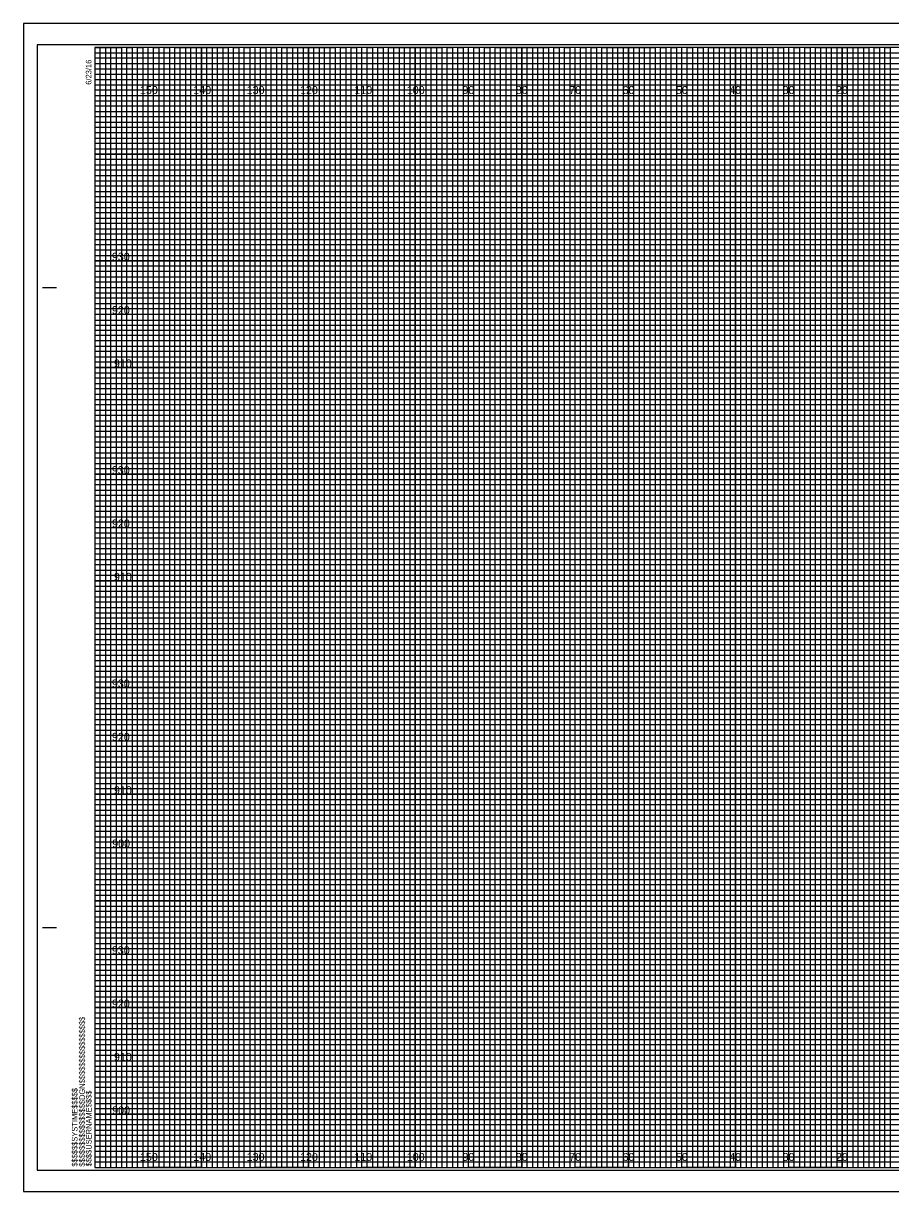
# Model space of a CAD drawing. Extents: x -13 to 323, y -4 to 3074.
# Drawn here: x -13.4 to 149.1, y 215.5 to 434.5 of the extents above; entities that cross this region are included whole.
import ezdxf

# ---------------------------------------------------------------- set-up
doc = ezdxf.new("R2010")
doc.units = 0
for name, color, linetype in [('Prop XS Elevation Labels', 7, 'Continuous'), ('Prop XS Offset Labels', 7, 'Continuous'), ('Sheet Cross Section CELL', 7, 'Continuous'), ('Sheet Cross Section Grid Major CELL', 7, 'Continuous'), ('Sheet Cross Section Grid Middle CELL', 7, 'Continuous'), ('Sheet Cross Section Grid Minor 1 CELL', 7, 'Continuous'), ('Sheet Cross Section Grid Minor 2 CELL', 7, 'Continuous'), ('Sheet Cutting Line CELL', 7, 'Continuous'), ('Sheet DOT Grid CELL', 7, 'Continuous'), ('Sheet Plot Border Inside CELL', 7, 'Continuous'), ('Sheet Plot Border Outside CELL', 7, 'Continuous')]:
    doc.layers.add(name, color=color, linetype=linetype)

msp = doc.modelspace()

# ---------------------------------------------------------------- linework, layer by layer
at = {"layer": 'Sheet Cross Section CELL'}
for p, q in [((-9.8, 385), (-7.3, 385)), ((-9.7, 385), (-7.2, 385)), ((-9.8, 265), (-7.3, 265)), ((-9.7, 265), (-7.2, 265)), ((0, 220), (0, 220)), ((0, 220), (0, 220)), ((0, 220), (0, 220)), ((0, 220), (0, 220)), ((0, 220), (0, 220)), ((0, 220), (0, 220)), ((0, 220), (0, 220))]:
    msp.add_line(p, q, dxfattribs=at)
msp.add_lwpolyline([(320, 430), (0, 430), (0, 220), (320, 220)], close=True, dxfattribs=at)
at = {"layer": 'Sheet Cross Section Grid Major CELL'}
for p, q in [((10, 430), (0, 430)), ((10, 220), (10, 430)), ((30, 430), (20, 430)), ((20, 430), (20, 220)), ((30, 220), (30, 430)), ((50, 430), (40, 430)), ((40, 430), (40, 220)), ((50, 220), (50, 430)), ((70, 430), (60, 430)), ((60, 430), (60, 220)), ((70, 220), (70, 430)), ((90, 430), (80, 430)), ((80, 430), (80, 220)), ((90, 220), (90, 430)), ((110, 430), (100, 430)), ((100, 430), (100, 220)), ((110, 220), (110, 430)), ((130, 430), (120, 430)), ((120, 430), (120, 220)), ((130, 220), (130, 430)), ((150, 430), (140, 430)), ((140, 430), (140, 220)), ((20, 220), (10, 220)), ((40, 220), (30, 220)), ((60, 220), (50, 220)), ((80, 220), (70, 220)), ((100, 220), (90, 220)), ((120, 220), (110, 220)), ((140, 220), (130, 220))]:
    msp.add_line(p, q, dxfattribs=at)
for points in [[(0, 420), (320, 420), (320, 410), (0, 410)], [(0, 400), (320, 400), (320, 390), (0, 390)], [(0, 380), (320, 380), (320, 370), (0, 370)], [(0, 360), (320, 360), (320, 350), (0, 350)], [(0, 340), (320, 340), (320, 330), (0, 330)], [(0, 320), (320, 320), (320, 310), (0, 310)], [(0, 300), (320, 300), (320, 290), (0, 290)], [(0, 280), (320, 280), (320, 270), (0, 270)], [(0, 260), (320, 260), (320, 250), (0, 250)], [(0, 240), (320, 240), (320, 230), (0, 230)]]:
    msp.add_lwpolyline(points, dxfattribs=at)
at = {"layer": 'Sheet Cross Section Grid Middle CELL'}
for points in [[(0, 430), (5, 430), (5, 220), (15, 220), (15, 430), (25, 430), (25, 220), (35, 220), (35, 430), (45, 430), (45, 220), (55, 220), (55, 430), (65, 430), (65, 220), (75, 220), (75, 430), (85, 430), (85, 220), (95, 220), (95, 430), (105, 430), (105, 220), (115, 220), (115, 430), (125, 430), (125, 220), (135, 220), (135, 430), (145, 430), (145, 220), (155, 220)], [(0, 425), (275, 425)], [(0, 405), (320, 405), (320, 415), (0, 415)], [(0, 385), (320, 385), (320, 395), (0, 395)], [(0, 365), (320, 365), (320, 375), (0, 375)], [(0, 345), (320, 345), (320, 355), (0, 355)], [(0, 325), (320, 325), (320, 335), (0, 335)], [(0, 305), (320, 305), (320, 315), (0, 315)], [(0, 285), (320, 285), (320, 295), (0, 295)], [(0, 265), (320, 265), (320, 275), (0, 275)], [(0, 245), (320, 245), (320, 255), (0, 255)], [(0, 225), (320, 225), (320, 235), (0, 235)]]:
    msp.add_lwpolyline(points, dxfattribs=at)
at = {"layer": 'Sheet Cross Section Grid Minor 1 CELL'}
for p, q in [((0, 429), (260, 429)), ((260, 427.98), (0, 427.98)), ((0, 427.98), (0, 427)), ((0, 427), (260, 427)), ((260, 425.89), (0, 425.89)), ((0, 425.89), (0, 424)), ((0, 424), (320, 424))]:
    msp.add_line(p, q, dxfattribs=at)
for points in [[(0, 423), (270, 423), (320, 423), (320, 422), (0, 422)], [(0, 421), (320, 421), (320, 419), (0, 419)], [(0, 418), (320, 418), (320, 417), (0, 416.98)], [(0, 416), (320, 416), (320, 414), (0, 414)], [(0, 413), (320, 413), (320, 412), (0, 412)], [(0, 411), (320, 411), (320, 409), (0, 409)], [(0, 408), (320, 408), (320, 407), (0, 407)], [(0, 406), (320, 406), (320, 404), (0, 404)], [(0, 403), (320, 403), (320, 402), (0, 402)], [(0, 401), (320, 401), (320, 399), (0, 399)], [(0, 398), (320, 398), (320, 397), (0, 397)], [(0, 396), (320, 396), (320, 393.95), (320, 393), (320, 392), (0, 392)], [(0, 394), (320, 394), (320, 393), (0, 393)], [(0, 391), (320, 391), (320, 389), (0, 389.03)], [(0, 389.03), (320, 389), (320, 388), (0, 388)], [(0, 387), (320, 387), (320, 386), (0, 386)], [(0, 384), (320, 384), (320, 383), (0, 383)], [(0, 382), (320, 382), (320, 381), (0, 381)], [(-0.07, 378.89), (320, 378.89), (320, 377.88), (-0.07, 377.88)], [(0, 377), (320, 377), (320, 376), (0, 376)], [(0, 374), (320, 374), (320, 373), (0, 373)], [(0, 372), (320, 372), (320, 371), (0, 371)], [(0, 369), (320, 369), (320, 368), (0, 368)], [(0, 367), (320, 367), (320, 366), (0, 366)], [(0, 364), (320, 364), (320, 363), (0, 363)], [(0, 362), (320, 362), (320, 361), (0, 361)], [(0, 359), (320, 359), (319.99, 357.98), (0, 358)], [(0, 357), (320, 357), (320, 356), (0, 356)], [(0, 354), (320, 354), (320, 353), (0, 353)], [(0, 352), (320, 352), (320, 351), (0, 351)], [(0, 349), (320, 349), (320, 348), (0, 348)], [(0, 347), (320, 347), (320, 346), (0, 346)], [(0, 344), (320, 344), (320, 343), (0, 343)], [(0, 342), (320, 342), (320, 341), (0, 341)], [(0, 339), (320, 339), (320, 338), (0, 338)], [(0, 336.99), (320.07, 336.91), (320, 336), (0, 336)], [(0, 334), (320, 334), (320, 333), (0, 333)], [(0, 332), (320, 332), (320, 331), (0, 331)], [(0, 329), (320, 329), (320, 328), (0, 328)], [(0, 327), (320, 327), (320, 326), (0, 326)], [(0, 324), (320, 324), (320, 323), (0, 323)], [(0, 322), (320, 322), (320, 321), (0, 321)], [(0, 319), (320, 319), (320, 318), (0, 318)], [(0, 317), (320, 317), (320, 316), (0, 316)], [(0, 314), (320, 314), (320, 313), (0, 313)], [(0, 312), (320, 312), (320, 311), (0, 311)], [(0, 309), (320, 309), (320, 308), (0, 308)], [(0, 307), (320, 307), (320, 306), (0, 306)], [(0, 304), (320, 304), (320, 303), (0, 303)], [(0, 302), (320, 302), (320, 301), (0, 301)], [(0, 299), (320, 299), (319.99, 297.98), (0, 298)], [(0, 297), (320, 297), (320, 296), (0, 296)], [(0, 294), (320, 294), (320, 293), (0, 293)], [(0, 292), (320, 292), (320, 291), (0, 291)], [(0, 289), (320, 289), (320, 288), (0, 288)], [(0, 287), (320, 287), (320, 286), (0, 286)], [(0, 284), (320, 284), (320, 283), (0, 283)], [(0, 282), (320, 282), (320, 281), (0, 281)], [(0, 279), (320, 279), (320, 278), (0, 278)], [(0, 276.99), (320.07, 276.91), (320, 276), (0, 276)], [(0, 274), (320, 274), (320, 273), (0, 273)], [(0, 272), (320, 272), (320, 271), (0, 271)], [(0, 269), (320, 269), (320, 268), (0, 268)], [(0, 267), (320, 267), (320, 266), (0, 266)], [(0, 264), (320, 264), (320, 263), (0, 263)], [(0, 262), (320, 262), (320, 261), (0, 261)], [(0, 259), (320, 259), (320, 258), (0, 258)], [(0, 257), (320, 257), (320, 256), (0, 256)], [(0, 254), (320, 254), (320, 253), (0, 253)], [(0, 252), (320, 252), (320, 251), (0, 251)], [(0, 249), (320, 249), (320, 248), (0, 248)], [(0, 247), (320, 247), (320, 246), (0, 246)], [(0, 244), (320, 244), (320, 243), (0, 243)], [(0, 242), (320, 242), (320, 241), (0, 241)], [(0, 239), (320, 239), (320, 238), (0, 238)], [(0, 237), (320, 237), (320, 236), (0, 236)], [(0, 234), (320, 234), (320, 233), (0, 233)], [(0, 232), (320, 232), (320, 231), (0, 231)], [(0, 229), (320, 229), (320, 228), (0, 228)], [(0, 227), (320, 227), (320, 226), (0, 226)], [(0, 224), (320, 224), (320, 223), (0, 223)], [(0, 222), (320, 222), (320, 221), (0, 221)]]:
    msp.add_lwpolyline(points, dxfattribs=at)
at = {"layer": 'Sheet Cross Section Grid Minor 2 CELL'}
for points in [[(0, 220), (1, 220), (1, 430), (2, 430), (2, 220)], [(2, 220), (3, 220), (3, 430), (4, 430), (4, 220)], [(5, 220), (6, 220), (6, 430), (7, 430), (7, 220)], [(7, 220), (8, 220), (8, 430), (9, 430), (9, 220)], [(10, 220), (11, 220), (11, 430), (12, 430), (12, 220)], [(12, 220), (13, 220), (13, 430), (14, 430), (14, 220)], [(15, 220), (16, 220), (16, 430), (17, 430), (17, 220)], [(17, 220), (18, 220), (18, 430), (19, 430), (19, 220)], [(20, 220), (21, 220), (21, 430), (22, 430), (22, 220)], [(22, 220), (23, 220), (23, 430), (24, 430), (24, 220)], [(25, 220), (26, 220), (26, 430), (27, 430), (27, 220)], [(27, 220), (28, 220), (28, 430), (29, 430), (29, 220)], [(30, 220), (31, 220), (31, 430), (32, 430), (32, 220)], [(32, 220), (33, 220), (33, 430), (34, 430), (34, 220)], [(35, 220), (36, 220), (36, 430), (37, 430), (37, 220)], [(37, 220), (38, 220), (38, 430), (39, 430), (39, 220)], [(40, 220), (41, 220), (41, 430), (42, 430), (42, 220)], [(42, 220), (43, 220), (43, 430), (44, 430), (44, 220)], [(45, 220), (46, 220), (46, 430), (47, 430), (47, 220)], [(47, 220), (48, 220), (48, 430), (49, 430), (49, 220)], [(50, 220), (51, 220), (51, 430), (52, 430), (52, 220)], [(52, 220), (53, 220), (53, 430), (54, 430), (54, 220)], [(55, 220), (56, 220), (56, 430), (57, 430), (57, 220)], [(57, 220), (58, 220), (58, 430), (59, 430), (59, 220)], [(60, 220), (61, 220), (61, 430), (62, 430), (62, 220)], [(62, 220), (63, 220), (63, 430), (64, 430), (64, 220)], [(65, 220), (66, 220), (66, 430), (67, 430), (67, 220)], [(67, 220), (68, 220), (68, 430), (69, 430), (69, 220)], [(70, 220), (71, 220), (71, 430), (72, 430), (72, 220)], [(72, 220), (73, 220), (73, 430), (74, 430), (74, 220)], [(75, 220), (76, 220), (76, 430), (77, 430), (77, 220)], [(77, 220), (78, 220), (78, 430), (79, 430), (79, 220)], [(80, 220), (81, 220), (81, 430), (82, 430), (82, 220)], [(82, 220), (83, 220), (83, 430), (84, 430), (84, 220)], [(85, 220), (86, 220), (86, 430), (87, 430), (87, 220)], [(87, 220), (88, 220), (88, 430), (89, 430), (89, 220)], [(90, 220), (91, 220), (91, 430), (92, 430), (92, 220)], [(92, 220), (93, 220), (93, 430), (94, 430), (94, 220)], [(95, 220), (96, 220), (96, 430), (97, 430), (97, 220)], [(97, 220), (98, 220), (98, 430), (99, 430), (99, 220)], [(100, 220), (101, 220), (101, 430), (102, 430), (102, 220)], [(102, 220), (103, 220), (103, 430), (104, 430), (104, 220)], [(105, 220), (106, 220), (106, 430), (107, 430), (107, 220)], [(107, 220), (108, 220), (108, 430), (109, 430), (109, 220)], [(110, 220), (111, 220), (111, 430), (112, 430), (112, 220)], [(112, 220), (113, 220), (113, 430), (114, 430), (114, 220)], [(115, 220), (116, 220), (116, 430), (117, 430), (117, 220)], [(117, 220), (118, 220), (118, 430), (119, 430), (119, 220)], [(120, 220), (121, 220), (121, 430), (122, 430), (122, 220)], [(122, 220), (123, 220), (123, 430), (124, 430), (124, 220)], [(125, 220), (126, 220), (126, 430), (127, 430), (127, 220)], [(127, 220), (128, 220), (128, 430), (129, 430), (129, 220)], [(130, 220), (131, 220), (131, 430), (132, 430), (132, 220)], [(132, 220), (133, 220), (133, 430), (134, 430), (134, 220)], [(135, 220), (136, 220), (136, 430), (137, 430), (137, 220)], [(137, 220), (138, 220), (138, 430), (139, 430), (139, 220)], [(140, 220), (141, 220), (141, 430), (142, 430), (142, 220)], [(142, 220), (143, 220), (143, 430), (144, 430), (144, 220)], [(145, 220), (146, 220), (146, 430), (147, 430), (147, 220)], [(147, 220), (148, 220), (148, 430), (149, 430), (149, 220)]]:
    msp.add_lwpolyline(points, dxfattribs=at)
at = {"layer": 'Sheet Cutting Line CELL'}
for p, q in [((323.3, 434.5), (-13.4, 434.5)), ((-13.4, 434.5), (-13.4, 215.5)), ((-13.4, 215.5), (323.3, 215.5))]:
    msp.add_line(p, q, dxfattribs=at)
at = {"layer": 'Sheet DOT Grid CELL'}
for p, q in [((10, 220), (10, 430)), ((20, 220), (20, 430)), ((30, 220), (30, 430)), ((40, 220), (40, 430)), ((50, 220), (50, 430)), ((60, 220), (60, 430)), ((70, 220), (70, 430)), ((80, 220), (80, 430)), ((90, 220), (90, 430)), ((100, 220), (100, 430)), ((110, 220), (110, 430)), ((120, 220), (120, 430)), ((130, 220), (130, 430)), ((140, 220), (140, 430)), ((0, 420), (320, 420)), ((0, 410), (320, 410)), ((0, 400), (320, 400)), ((0, 390), (320, 390)), ((0, 380), (320, 380)), ((0, 370), (320, 370)), ((0, 360), (320, 360)), ((0, 350), (320, 350)), ((0, 340), (320, 340)), ((0, 330), (320, 330)), ((0, 320), (320, 320)), ((0, 310), (320, 310)), ((0, 300), (320, 300)), ((0, 290), (320, 290)), ((0, 280), (320, 280)), ((0, 270), (320, 270)), ((0, 260), (320, 260)), ((0, 250), (320, 250)), ((0, 240), (320, 240)), ((0, 230), (320, 230))]:
    msp.add_line(p, q, dxfattribs=at)
at = {"layer": 'Sheet Plot Border Inside CELL'}
msp.add_lwpolyline([(-10.8, 219.5), (322.4, 219.5), (322.4, 430.5), (-10.8, 430.5)], close=True, dxfattribs=at)
at = {"layer": 'Sheet Plot Border Outside CELL'}
msp.add_lwpolyline([(-13.4, 215.5), (323.3, 215.5), (323.3, 434.5), (-13.4, 434.5)], close=True, dxfattribs=at)

# ---------------------------------------------------------------- texts
at = {"layer": 'Prop XS Elevation Labels'}
for s, p in [('930', (3.18, 390)), ('920', (3.19, 380)), ('910', (3.57, 370)), ('930', (3.18, 350)), ('920', (3.19, 340)), ('910', (3.57, 330)), ('930', (3.18, 310)), ('920', (3.19, 300)), ('910', (3.57, 290)), ('900', (3.24, 280)), ('930', (3.18, 260)), ('920', (3.19, 250)), ('910', (3.57, 240)), ('900', (3.24, 230))]:
    msp.add_text(s, height=1.5, dxfattribs=at).set_placement(p)
at = {"layer": 'Prop XS Offset Labels'}
for s, p in [('150', (8.44, 421.25)), ('140', (18.44, 421.25)), ('130', (28.44, 421.25)), ('120', (38.44, 421.25)), ('110', (48.62, 421.25)), ('100', (58.44, 421.25)), ('90', (68.86, 421.25)), ('80', (78.86, 421.25)), ('70', (88.86, 421.25)), ('60', (98.86, 421.25)), ('50', (108.86, 421.25)), ('40', (118.86, 421.25)), ('30', (128.86, 421.25)), ('20', (138.86, 421.25)), ('150', (8.44, 221.25)), ('140', (18.44, 221.25)), ('130', (28.44, 221.25)), ('120', (38.44, 221.25)), ('110', (48.62, 221.25)), ('100', (58.44, 221.25)), ('90', (68.86, 221.25)), ('80', (78.86, 221.25)), ('70', (88.86, 221.25)), ('60', (98.86, 221.25)), ('50', (108.86, 221.25)), ('40', (118.86, 221.25)), ('30', (128.86, 221.25)), ('20', (138.86, 221.25))]:
    msp.add_text(s, height=1.5, dxfattribs=at).set_placement(p)
at = {"layer": 'Sheet Cross Section CELL'}
for s, p in [('6/23/16', (-0.65, 423)), ('$$$$$$$$$$$$$$$$DGN$$$$$$$$$$$$$$$$', (-1.88, 220.18)), ('$$$$$$SYSTIME$$$$$', (-3.26, 220.18)), ('$$$$USERNAME$$$$', (-0.62, 220.23))]:
    msp.add_text(s, height=1.05, rotation=90, dxfattribs=at).set_placement(p)

doc.saveas('drawing.dxf')
